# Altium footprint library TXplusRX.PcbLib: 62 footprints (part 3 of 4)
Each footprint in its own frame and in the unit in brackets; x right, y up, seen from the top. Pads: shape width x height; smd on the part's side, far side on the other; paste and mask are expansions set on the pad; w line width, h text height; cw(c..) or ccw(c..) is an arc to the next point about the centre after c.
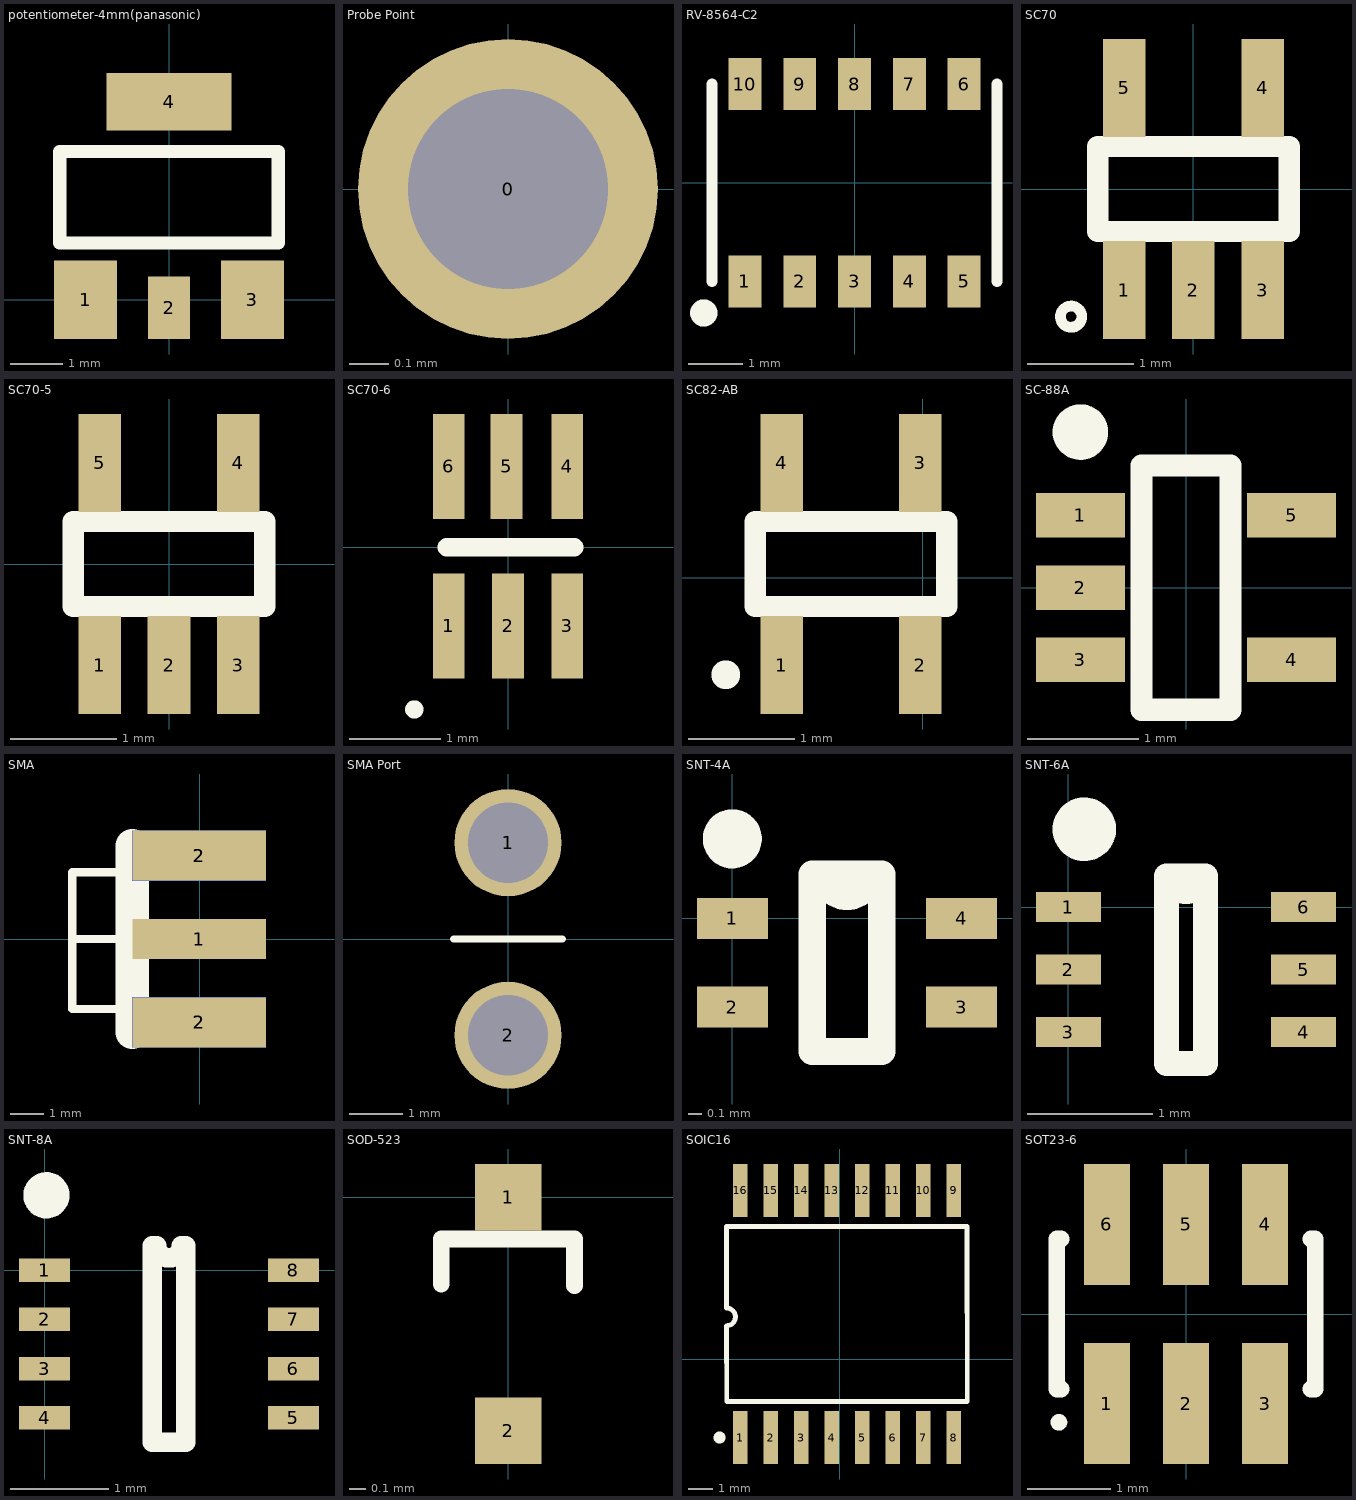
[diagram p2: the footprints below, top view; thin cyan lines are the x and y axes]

## potentiometer-4mm(panasonic) [mm]
pads (4):
  rect 1.2x1.5 smd: 1(-1.6,0) 3(1.6,0)
  rect 0.8x1.2 smd: 2(0,-0.15)
  rect 2.4x1.1 smd: 4(0,3.8)
Top Overlay:
  lines w0.254: -2.095,1.092 2.095,1.092 2.095,2.845 -2.095,2.845 -2.095,1.092

## Probe Point [mil] "35mil Pad, 20mil hole size"
pads (1):
  round 30 hole 20: 0(0,0)

## RV-8564-C2 [mm] "RV-8564-C2 RTC Package: LCC, 10-Pins, Body 5.2x3.4mm (max), Pitch 1.00mm, IPC Medium Density"
height 1.2
pads (10):
  rect 0.6x0.95 smd: 1(-2,-1.8) 2(-1,-1.8) 3(0,-1.8) 4(1,-1.8) 5(2,-1.8) 6(2,1.8) 7(1,1.8) 8(0,1.8) 9(-1,1.8) 10(-2,1.8)
Top Overlay:
  circle w0.25: c-2.75,-2.375 r0.125
  lines w0.2: -2.6,-1.8 -2.6,1.8 ; 2.6,-1.8 2.6,1.8

## SC70 [mm] "Ultra low Power LDO - TI"
height 1.1
pads (5):
  rect 0.4x0.92 smd: 1(-0.65,-0.95) 2(0,-0.95) 3(0.65,-0.95) 4(0.65,0.95) 5(-0.65,0.95)
Top Overlay:
  circle w0.1: c-1.15,-1.2 r0.1
  lines w0.2: -0.9,-0.4 0.9,-0.4 0.9,0.4 -0.9,0.4 -0.9,-0.4

## SC70-5 [mm] "SC70-5"
pads (5):
  rect 0.4x0.92 smd: 1(-0.65,-0.95) 2(0,-0.95) 3(0.65,-0.95) 4(0.65,0.95) 5(-0.65,0.95)
Top Overlay:
  lines w0.2: -0.9,-0.4 -0.9,0.4 0.9,0.4 0.9,-0.4 -0.9,-0.4

## SC70-6 [mm] "DIP; 24 Leads; Row Spacing 15.24 mm; Pitch 2.54 mm"
height 5.72
pads (6):
  rect 0.35x1.15 smd: 1(-0.652,-0.863) 2(-0.002,-0.863) 3(0.648,-0.863) 4(0.648,0.887) 5(-0.017,0.887) 6(-0.652,0.887)
Top Overlay:
  circle w0.1: c-1.03,-1.779 r0.05
  lines w0.2: -0.675,-0.001 0.725,-0.001

## SC82-AB [mm]
pads (4):
  rect 0.4x0.92 smd: 1(-1.323,-0.823) 2(-0.023,-0.823) 3(-0.023,1.077) 4(-1.323,1.077)
Top Overlay:
  circle w0.254: c-1.849,-0.914 r0.008
  lines w0.2: -1.573,-0.273 -1.573,0.527 0.227,0.527 0.227,-0.273 -1.573,-0.273

## SC-88A [mm] "SC-88A 5-Leads, Body 2.2x2.2mm (max), Pitch 0.65mm, IPC Medium Density"
height 1
pads (5):
  rect 0.8x0.4 smd: 1(-0.95,0.65) 2(-0.95,0) 3(-0.95,-0.65) 4(0.95,-0.65) 5(0.95,0.65)
Top Overlay:
  circle w0.25: c-0.95,1.4 r0.125
  lines w0.2: -0.4,-1.1 -0.4,1.1 0.4,1.1 0.4,-1.1 -0.4,-1.1

## SMA [mm]
pads (5):
  rect 4x1.2 smd: 1(-0.023,0.002)
  rect 4x1.5 smd: 2(-0.023,-2.498) 2(-0.023,2.502)
  rect 4x1.5 smd far side: 2(-0.023,-2.498) 2(-0.023,2.502)
Top Overlay:
  lines w0.254: -3.83,0.002 -2.03,0.002 ; -2.03,2.002 -3.83,2.002 -3.83,-2.098 -1.93,-2.098
  lines w1: -2.03,-2.798 -2.03,2.802

## SMA Port [mm] "SMA port for wisp"
pads (2):
  round 2 hole 1.5: 1(0,1.796) 2(0,-1.796)
Top Overlay:
  lines w0.127: -1.016,0 1.016,0

## SNT-4A [mm]
pads (4):
  rect 0.52x0.3 smd: 1(0,0) 2(0,-0.65) 3(1.68,-0.65) 4(1.68,0)
Top Overlay:
  circle w0.254: c-0.001,0.584 r0.09
  lines w0.2: 0.585,-0.975 1.095,-0.975 1.095,0.325 0.677,0.325 ccw(c0.84,0.325) 1.002,0.325 0.585,0.325 0.585,-0.975

## SNT-6A [mm]
pads (6):
  rect 0.52x0.24 smd: 1(0,0) 2(0,-0.5) 3(0,-1) 4(1.88,-1) 5(1.88,-0.5) 6(1.88,0)
Top Overlay:
  circle w0.254: c0.127,0.622 r0.127
  lines w0.2: 0.785,-1.25 1.095,-1.25 1.095,0.25 0.815,0.25 ccw(c0.94,0.25) 1.065,0.25 0.785,0.25 0.785,-1.25

## SNT-8A [mm]
pads (8):
  rect 0.52x0.24 smd: 1(0,0) 2(0,-0.5) 3(0,-1) 4(0,-1.5) 5(2.53,-1.5) 6(2.53,-1) 7(2.53,-0.5) 8(2.53,0)
Top Overlay:
  circle w0.254: c0.019,0.762 r0.108
  lines w0.2: 1.095,-1.75 1.435,-1.75 1.435,0.25 1.39,0.25 cw(c1.265,0.25) 1.14,0.25 1.095,0.25 1.095,-1.75

## SOD-523 [mm] "SOD-523 Footprint"
height 1
pads (2):
  rect 0.4x0.4 smd: 1(0,0) 2(0,-1.4)
Top Overlay:
  lines w0.1: -0.401,-0.521 -0.401,-0.248 ; -0.4,-0.25 0.4,-0.25 ; 0.399,-0.531 0.399,-0.258

## SOIC16 [mm] "SOIC 16"
height 0.508
pads (16):
  rect 0.6x2.2 smd: 1(-4.153,-3.26) 2(-2.883,-3.26) 3(-1.613,-3.26) 4(-0.343,-3.26) 5(0.927,-3.26) 6(2.197,-3.26) 7(3.467,-3.26) 8(4.737,-3.26) 9(4.737,7.007) 10(3.467,7.007) 11(2.197,7.007) 12(0.927,7.007) 13(-0.343,7.007) 14(-1.613,7.007) 15(-2.883,7.007) 16(-4.153,7.007)
Top Overlay:
  circle w0.25: c-5.003,-3.26 r0.125
  lines w0.2: -4.712,1.372 -4.708,-1.76 5.292,-1.76 5.283,5.512 ; -4.712,1.386 ccw(c-4.712,1.753) -4.712,2.119 ; -4.712,2.121 -4.712,5.512 ; -4.708,5.507 5.292,5.507

## SOT23-6 [mm] "SOT-457/SC-74; 6 Leads; Body 3 x 3 mm, inc. leads (LxW max)"
height 1.45
pads (6):
  rect 0.55x1.45 smd: 1(-0.95,-1.075) 2(0,-1.075) 3(0.95,-1.075) 4(0.95,1.075) 5(0,1.075) 6(-0.95,1.075)
Top Overlay:
  circle w0.1: c-1.525,-1.3 r0.05
  lines w0.2: -1.5,-0.9 -1.55,-0.9 -1.55,0.9 -1.5,0.9 ; 1.5,-0.9 1.55,-0.9 1.55,0.9 1.5,0.9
